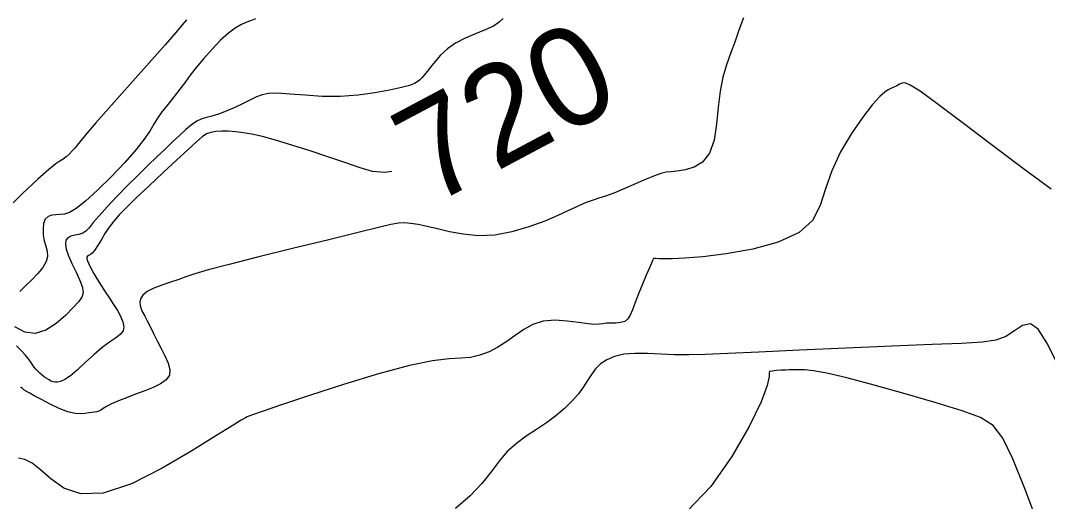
# Model space of a CAD drawing. Extents: x 2566142 to 2571431, y 418755 to 421584.
# Drawn here: x 2568476.3 to 2568684.4, y 419764 to 419861.5 of the extents above; entities that cross this region are included whole.
import ezdxf

# ---------------------------------------------------------------- set-up
doc = ezdxf.new("R2010")
doc.units = 0
for name, color, linetype in [('Contour_ADS_Label_Major', 7, 'Continuous'), ('Contour_ADS_Major', 7, 'Continuous'), ('Contour_ADS_Minor', 7, 'Continuous')]:
    doc.layers.add(name, color=color, linetype=linetype)

msp = doc.modelspace()

# ---------------------------------------------------------------- linework, layer by layer
at = {"layer": 'Contour_ADS_Major'}
msp.add_lwpolyline([(2568551.55, 419830.9), (2568550.13, 419830.68), (2568547.65, 419830.91), (2568545.11, 419831.61), (2568542.21, 419832.62), (2568538.77, 419833.81), (2568535.03, 419835.05), (2568531.33, 419836.22), (2568528.01, 419837.21), (2568525.33, 419837.94), (2568523.21, 419838.43), (2568521.47, 419838.74), (2568519.94, 419838.93), (2568518.49, 419839.03), (2568517.14, 419839.06), (2568515.92, 419838.99), (2568514.88, 419838.81), (2568514.02, 419838.5), (2568513.14, 419837.92), (2568511.98, 419836.92), (2568510.3, 419835.36), (2568507.95, 419833.16), (2568505.17, 419830.58), (2568502.33, 419827.92), (2568499.78, 419825.52), (2568497.8, 419823.62), (2568496.33, 419822.12), (2568495.2, 419820.84), (2568494.28, 419819.61), (2568493.43, 419818.3), (2568492.65, 419816.99), (2568491.95, 419815.81), (2568491.34, 419814.89), (2568490.83, 419814.31), (2568490.42, 419814), (2568490.11, 419813.85), (2568489.9, 419813.73), (2568489.78, 419813.55), (2568489.76, 419813.26), (2568489.88, 419812.8), (2568490.15, 419812.15), (2568490.59, 419811.28), (2568491.17, 419810.22), (2568491.86, 419809.04), (2568492.65, 419807.78), (2568493.49, 419806.5), (2568494.34, 419805.23), (2568495.18, 419803.97), (2568495.95, 419802.74), (2568496.6, 419801.55), (2568497.07, 419800.45), (2568497.27, 419799.45), (2568497.11, 419798.58), (2568496.54, 419797.85), (2568495.6, 419797.14), (2568494.36, 419796.32), (2568492.87, 419795.24), (2568491.22, 419793.83), (2568489.52, 419792.25), (2568487.9, 419790.74), (2568486.46, 419789.51), (2568485.32, 419788.74), (2568484.45, 419788.35), (2568483.79, 419788.23), (2568483.32, 419788.24), (2568482.97, 419788.28), (2568482.69, 419788.35), (2568482.42, 419788.47), (2568482.1, 419788.66), (2568481.69, 419788.92), (2568481.21, 419789.25), (2568480.71, 419789.62), (2568480.23, 419790.01), (2568479.81, 419790.41), (2568479.44, 419790.82), (2568479.11, 419791.22), (2568478.83, 419791.62), (2568478.58, 419792.03), (2568478.29, 419792.48), (2568477.88, 419793.03), (2568477.3, 419793.73), (2568476.49, 419794.6), (2568475.53, 419795.54)], dxfattribs=at)
at = {"layer": 'Contour_ADS_Minor'}
for points in [[(2568509.95, 419861.59), (2568509.11, 419860.57), (2568507.79, 419859.01), (2568505.62, 419856.52), (2568502.39, 419852.88), (2568498.56, 419848.58), (2568494.76, 419844.31), (2568491.59, 419840.73), (2568489.53, 419838.35), (2568488.38, 419836.97), (2568487.78, 419836.2), (2568487.37, 419835.69), (2568486.86, 419835.11), (2568486.24, 419834.48), (2568485.58, 419833.87), (2568484.94, 419833.37), (2568484.32, 419832.97), (2568483.48, 419832.4), (2568482.09, 419831.31), (2568479.86, 419829.35), (2568476.64, 419826.34), (2568472.92, 419822.73)], [(2568523.92, 419861.83), (2568522.94, 419861.4), (2568521.97, 419861.03), (2568520.95, 419860.59), (2568519.79, 419859.94), (2568518.44, 419858.92), (2568516.85, 419857.45), (2568515.14, 419855.66), (2568513.45, 419853.77), (2568511.94, 419851.96), (2568510.73, 419850.41), (2568509.73, 419849.06), (2568508.84, 419847.84), (2568507.94, 419846.65), (2568506.96, 419845.44), (2568505.94, 419844.19), (2568504.96, 419842.94), (2568504.08, 419841.69), (2568503.33, 419840.45), (2568502.51, 419839.08), (2568501.4, 419837.42), (2568499.75, 419835.31), (2568497.43, 419832.69), (2568494.69, 419829.82), (2568491.91, 419827.09), (2568489.46, 419824.85), (2568487.6, 419823.39), (2568486.26, 419822.59), (2568485.24, 419822.24), (2568484.36, 419822.15), (2568483.49, 419822.11), (2568482.65, 419822.02), (2568481.91, 419821.77), (2568481.34, 419821.24), (2568481.01, 419820.38), (2568480.89, 419819.28), (2568480.94, 419818.05), (2568481.15, 419816.84), (2568481.45, 419815.74), (2568481.71, 419814.71), (2568481.79, 419813.69), (2568481.53, 419812.62), (2568480.84, 419811.44), (2568479.81, 419810.19), (2568478.6, 419808.93), (2568477.36, 419807.7), (2568476.22, 419806.57)], [(2568574.09, 419861.89), (2568573.32, 419861.12), (2568572.13, 419860.34), (2568570.47, 419859.58), (2568568.51, 419858.79), (2568566.44, 419857.91), (2568564.48, 419856.89), (2568562.81, 419855.7), (2568561.43, 419854.41), (2568560.31, 419853.15), (2568559.41, 419852.02), (2568558.7, 419851.12), (2568558.14, 419850.42), (2568557.67, 419849.88), (2568557.25, 419849.45), (2568556.81, 419849.08), (2568556.17, 419848.72), (2568555.13, 419848.33), (2568553.49, 419847.88), (2568551.1, 419847.33), (2568548.11, 419846.78), (2568544.71, 419846.32), (2568541.09, 419846.08), (2568537.45, 419846.1), (2568533.99, 419846.31), (2568530.91, 419846.56), (2568528.4, 419846.72), (2568526.59, 419846.68), (2568525.27, 419846.43), (2568524.15, 419845.99)], [(2568622.82, 419862), (2568621.9, 419859.52), (2568621.04, 419857.06), (2568620.18, 419854.75), (2568619.36, 419852.45), (2568618.63, 419849.99), (2568618.07, 419847.17), (2568617.7, 419843.9), (2568617.36, 419840.46), (2568616.84, 419837.24), (2568615.94, 419834.59), (2568614.53, 419832.79), (2568612.79, 419831.73), (2568610.99, 419831.19), (2568609.38, 419830.96), (2568608.14, 419830.84), (2568607.12, 419830.71), (2568606.07, 419830.48), (2568604.77, 419830.03), (2568603.06, 419829.32), (2568601.04, 419828.43), (2568598.92, 419827.49), (2568596.87, 419826.64), (2568595.06, 419825.97), (2568593.49, 419825.45), (2568592.12, 419825.01), (2568590.92, 419824.6), (2568589.84, 419824.15), (2568588.68, 419823.59), (2568587.21, 419822.89), (2568585.21, 419821.98), (2568582.54, 419820.84), (2568579.35, 419819.66), (2568575.89, 419818.64), (2568572.4, 419818), (2568569.09, 419817.87), (2568566.03, 419818.17), (2568563.25, 419818.69), (2568560.8, 419819.28), (2568558.69, 419819.77), (2568556.89, 419820.14), (2568555.37, 419820.38), (2568554.1, 419820.48), (2568552.93, 419820.43), (2568551.38, 419820.14), (2568548.84, 419819.54), (2568544.75, 419818.52), (2568538.77, 419817.06), (2568531.7, 419815.34)], [(2568685.13, 419827.27), (2568679.56, 419831.4), (2568673.26, 419836.16), (2568667.11, 419840.82), (2568662, 419844.66), (2568658.59, 419847.13), (2568656.61, 419848.39), (2568655.57, 419848.82), (2568654.98, 419848.77), (2568654.42, 419848.55), (2568653.85, 419848.26), (2568653.26, 419847.95), (2568652.69, 419847.67), (2568652.13, 419847.42), (2568651.43, 419846.98), (2568650.43, 419846.08), (2568648.98, 419844.43), (2568646.98, 419841.86), (2568644.7, 419838.57), (2568642.49, 419834.87), (2568640.68, 419831.04), (2568639.46, 419827.37), (2568638.36, 419823.98), (2568636.78, 419820.98), (2568634.08, 419818.49), (2568629.87, 419816.57), (2568624.7, 419815.17), (2568619.33, 419814.22), (2568614.54, 419813.62), (2568610.91, 419813.3), (2568608.39, 419813.17), (2568606.74, 419813.17), (2568605.7, 419813.21), (2568605.08, 419813.24), (2568604.75, 419813.25), (2568604.61, 419813.23), (2568604.56, 419813.19), (2568604.51, 419813.11), (2568604.4, 419812.88), (2568604.17, 419812.34), (2568603.75, 419811.37), (2568603.12, 419809.88), (2568602.35, 419808.04), (2568601.56, 419806.11), (2568600.86, 419804.33), (2568600.32, 419802.88), (2568599.87, 419801.79), (2568599.38, 419801.02), (2568598.76, 419800.52), (2568597.91, 419800.27), (2568596.93, 419800.17), (2568595.93, 419800.16), (2568595.03, 419800.13), (2568594.3, 419800.05), (2568593.59, 419799.95), (2568592.67, 419799.91), (2568591.32, 419800.01), (2568589.4, 419800.29), (2568587.09, 419800.59), (2568584.62, 419800.74), (2568582.25, 419800.55), (2568580.15, 419799.89), (2568578.28, 419798.87), (2568576.54, 419797.66), (2568574.83, 419796.42), (2568573.06, 419795.3), (2568571.25, 419794.36), (2568569.39, 419793.65), (2568567.52, 419793.21), (2568565.56, 419793.05), (2568563.15, 419792.92), (2568559.82, 419792.53), (2568555.12, 419791.57), (2568548.83, 419789.88), (2568541.74, 419787.72), (2568534.85, 419785.5), (2568529.19, 419783.61), (2568525.51, 419782.36), (2568523.51, 419781.66), (2568522.61, 419781.32), (2568522.25, 419781.16), (2568521.88, 419780.98), (2568521.01, 419780.5), (2568519.18, 419779.39), (2568515.93, 419777.36), (2568511.02, 419774.27), (2568505.04, 419770.77), (2568498.78, 419767.64), (2568493.07, 419765.72), (2568488.53, 419765.56), (2568485.07, 419766.74)], [(2568524.15, 419845.99), (2568522.95, 419845.39), (2568521.45, 419844.64), (2568519.75, 419843.85), (2568518.02, 419843.1), (2568516.44, 419842.5), (2568515.12, 419842.11), (2568514.02, 419841.83), (2568513.03, 419841.53), (2568512.05, 419841.07), (2568510.98, 419840.34), (2568509.82, 419839.36), (2568508.54, 419838.19), (2568507.15, 419836.86), (2568505.63, 419835.42), (2568503.96, 419833.85), (2568502.14, 419832.1), (2568500.15, 419830.16), (2568498.01, 419828.02), (2568495.86, 419825.82), (2568493.88, 419823.73), (2568492.24, 419821.92), (2568491.07, 419820.52), (2568490.24, 419819.5), (2568489.59, 419818.8), (2568488.94, 419818.37), (2568488.16, 419818.12), (2568487.32, 419817.96), (2568486.53, 419817.78), (2568485.89, 419817.47), (2568485.51, 419816.95), (2568485.41, 419816.18), (2568485.58, 419815.14), (2568486.03, 419813.82), (2568486.75, 419812.22), (2568487.57, 419810.5), (2568488.34, 419808.83), (2568488.88, 419807.4), (2568489.04, 419806.32), (2568488.78, 419805.43), (2568488.09, 419804.5), (2568486.97, 419803.3), (2568485.43, 419801.73), (2568483.56, 419800.07), (2568481.48, 419798.71), (2568479.31, 419798.05), (2568477.18, 419798.36), (2568475.17, 419799.39)], [(2568531.7, 419815.34), (2568524.61, 419813.6), (2568518.57, 419812.07), (2568514.35, 419810.94), (2568511.65, 419810.13), (2568509.85, 419809.52), (2568508.37, 419809), (2568506.73, 419808.46), (2568504.99, 419807.87), (2568503.36, 419807.24), (2568502.02, 419806.57), (2568501.14, 419805.85), (2568500.66, 419805.12), (2568500.49, 419804.4), (2568500.55, 419803.71), (2568500.75, 419803.05), (2568501.06, 419802.38), (2568501.49, 419801.61), (2568502.01, 419800.65), (2568502.61, 419799.46), (2568503.28, 419798.09), (2568504.01, 419796.59), (2568504.79, 419795.05), (2568505.57, 419793.53), (2568506.22, 419792.08), (2568506.58, 419790.75), (2568506.5, 419789.6), (2568505.85, 419788.65), (2568504.72, 419787.86), (2568503.23, 419787.16), (2568501.5, 419786.48), (2568499.65, 419785.78), (2568497.82, 419785.07), (2568496.15, 419784.4), (2568494.77, 419783.79), (2568493.77, 419783.28), (2568493.09, 419782.87), (2568492.61, 419782.56), (2568492.21, 419782.34), (2568491.79, 419782.21), (2568491.33, 419782.13), (2568490.79, 419782.07), (2568490.17, 419781.98), (2568489.43, 419781.85), (2568488.52, 419781.77), (2568487.38, 419781.84), (2568485.94, 419782.19), (2568484.19, 419782.87), (2568482.32, 419783.76), (2568480.55, 419784.68), (2568479.11, 419785.46), (2568478.18, 419785.97), (2568477.66, 419786.25), (2568477.42, 419786.38), (2568477.32, 419786.44), (2568477.22, 419786.5), (2568477.12, 419786.57), (2568477.02, 419786.64), (2568476.93, 419786.71), (2568476.85, 419786.79), (2568476.79, 419786.86), (2568476.73, 419786.93), (2568476.68, 419787), (2568476.64, 419787.06), (2568476.6, 419787.12), (2568476.57, 419787.16), (2568476.53, 419787.17), (2568476.48, 419787.16), (2568476.41, 419787.11), (2568476.3, 419787.01)], [(2568686.27, 419792.2), (2568684.3, 419796.19), (2568682.55, 419798.97), (2568680.93, 419800), (2568679.35, 419799.67), (2568677.73, 419798.61), (2568675.99, 419797.46), (2568673.95, 419796.69), (2568671.14, 419796.28), (2568667.01, 419796.05), (2568661.03, 419795.84), (2568652.91, 419795.52), (2568643.56, 419795.11), (2568634.16, 419794.68), (2568625.89, 419794.29), (2568619.63, 419794), (2568615.1, 419793.81), (2568611.71, 419793.73), (2568608.86, 419793.76), (2568606.09, 419793.87), (2568603.38, 419793.99), (2568600.85, 419794.02), (2568598.6, 419793.85), (2568596.7, 419793.42), (2568595.14, 419792.75), (2568593.87, 419791.89), (2568592.84, 419790.88), (2568591.99, 419789.76), (2568591.21, 419788.55), (2568590.38, 419787.25), (2568589.37, 419785.86), (2568588.09, 419784.4), (2568586.55, 419782.91), (2568584.81, 419781.42), (2568582.9, 419779.99), (2568580.87, 419778.63), (2568578.8, 419777.27), (2568576.8, 419775.81), (2568574.96, 419774.15), (2568573.31, 419772.22), (2568571.67, 419770.04), (2568569.8, 419767.68), (2568567.44, 419765.2), (2568564.47, 419762.65)], [(2568682.64, 419759.12), (2568679.86, 419766.47), (2568677.36, 419772.7), (2568675.36, 419776.89), (2568673.4, 419779.43), (2568670.86, 419781.03), (2568667.13, 419782.38), (2568661.83, 419784.02), (2568655.59, 419785.86), (2568649.28, 419787.63), (2568643.77, 419789.08), (2568639.72, 419790.01), (2568637, 419790.5), (2568635.25, 419790.69), (2568634.14, 419790.72), (2568633.34, 419790.72), (2568632.7, 419790.71), (2568632.08, 419790.69), (2568631.34, 419790.66), (2568630.42, 419790.61), (2568629.44, 419790.54), (2568628.61, 419790.46), (2568628.11, 419790.34), (2568628.04, 419790.1), (2568628.03, 419789.34), (2568627.64, 419787.56), (2568626.38, 419784.26), (2568623.94, 419779.2), (2568620.44, 419773.14), (2568616.18, 419767.09), (2568611.43, 419762.06)], [(2568485.07, 419766.74), (2568482.44, 419768.6), (2568480.39, 419770.46), (2568478.69, 419771.79), (2568477.23, 419772.55), (2568475.95, 419772.84)]]:
    msp.add_lwpolyline(points, dxfattribs=at)

# ---------------------------------------------------------------- texts
at = {"layer": 'Contour_ADS_Label_Major'}
msp.add_text('720', height=20, rotation=28.0184, dxfattribs=at).set_placement((2568559.43, 419823.76))

doc.saveas('drawing.dxf')
